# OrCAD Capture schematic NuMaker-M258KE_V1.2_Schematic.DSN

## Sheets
1 Nu-Link2-Me: size A3; title: Nu-Link2-Me; rev: 1.0; company: CMHuang; note: Nu-Link2-Me
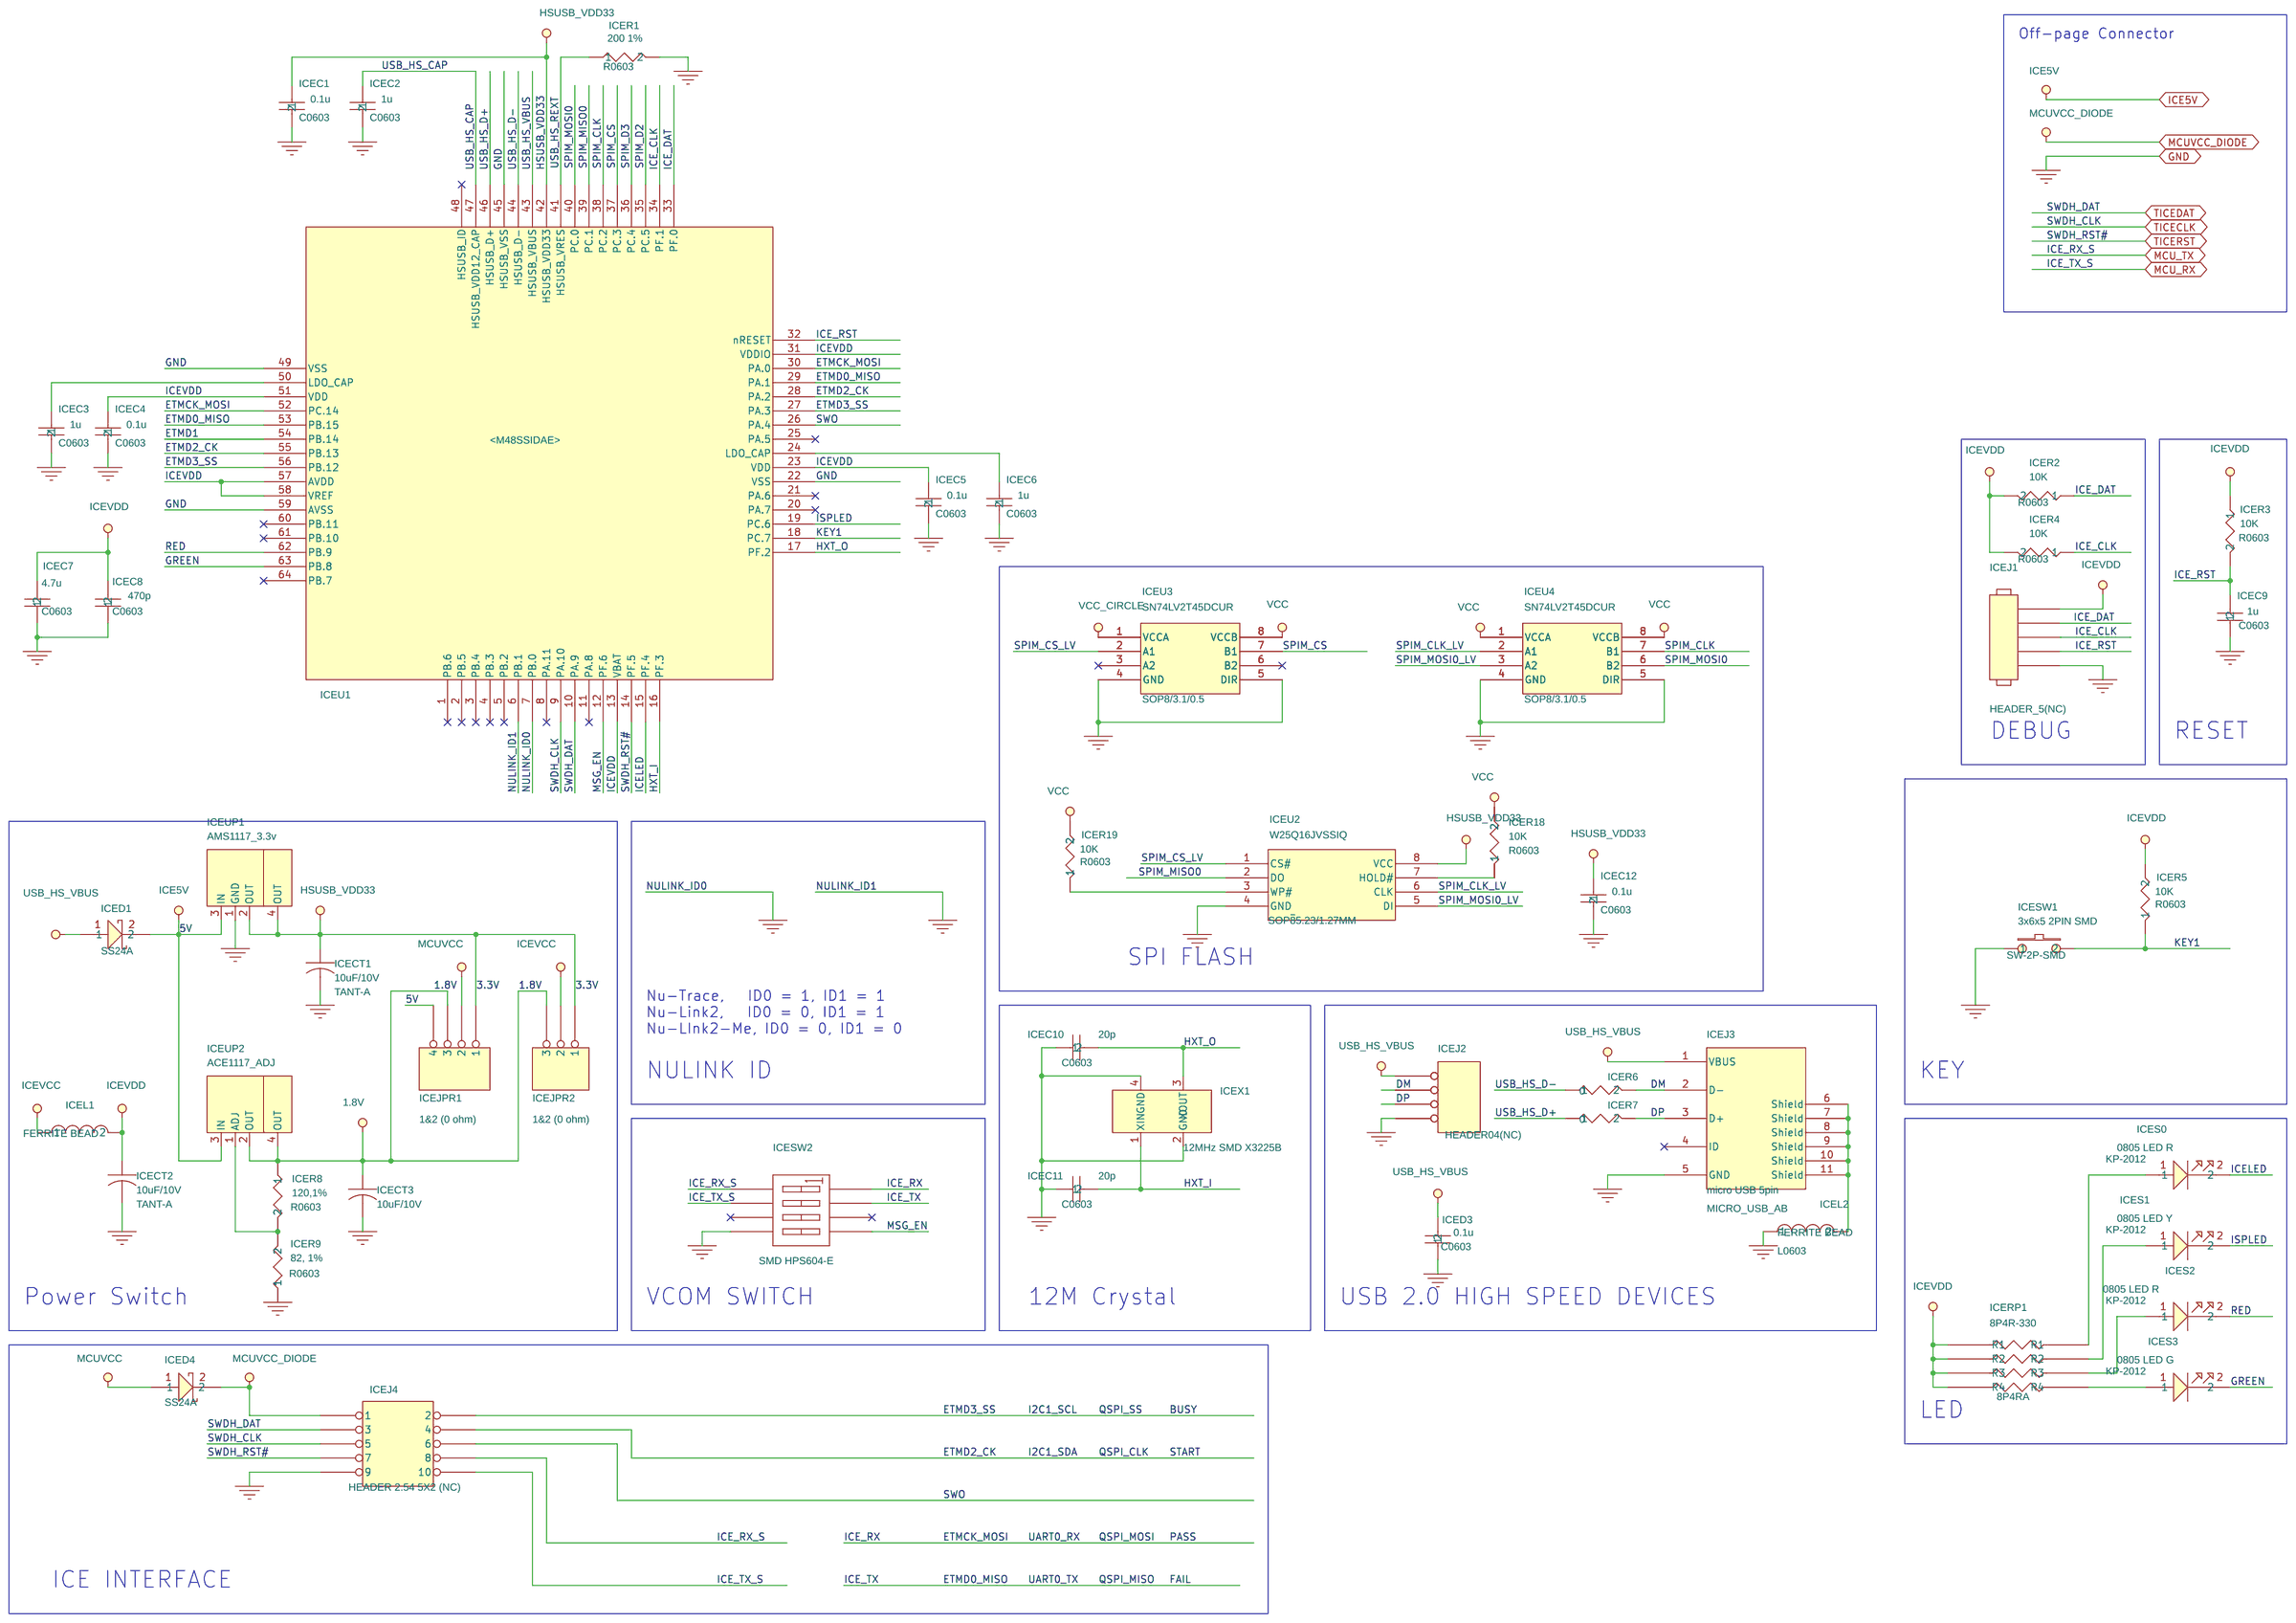
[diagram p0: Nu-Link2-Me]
2 M258KE3AE: size Custom; title: M258KE3AE; rev: v1.2; note: NuMaker-PFM-M258KE
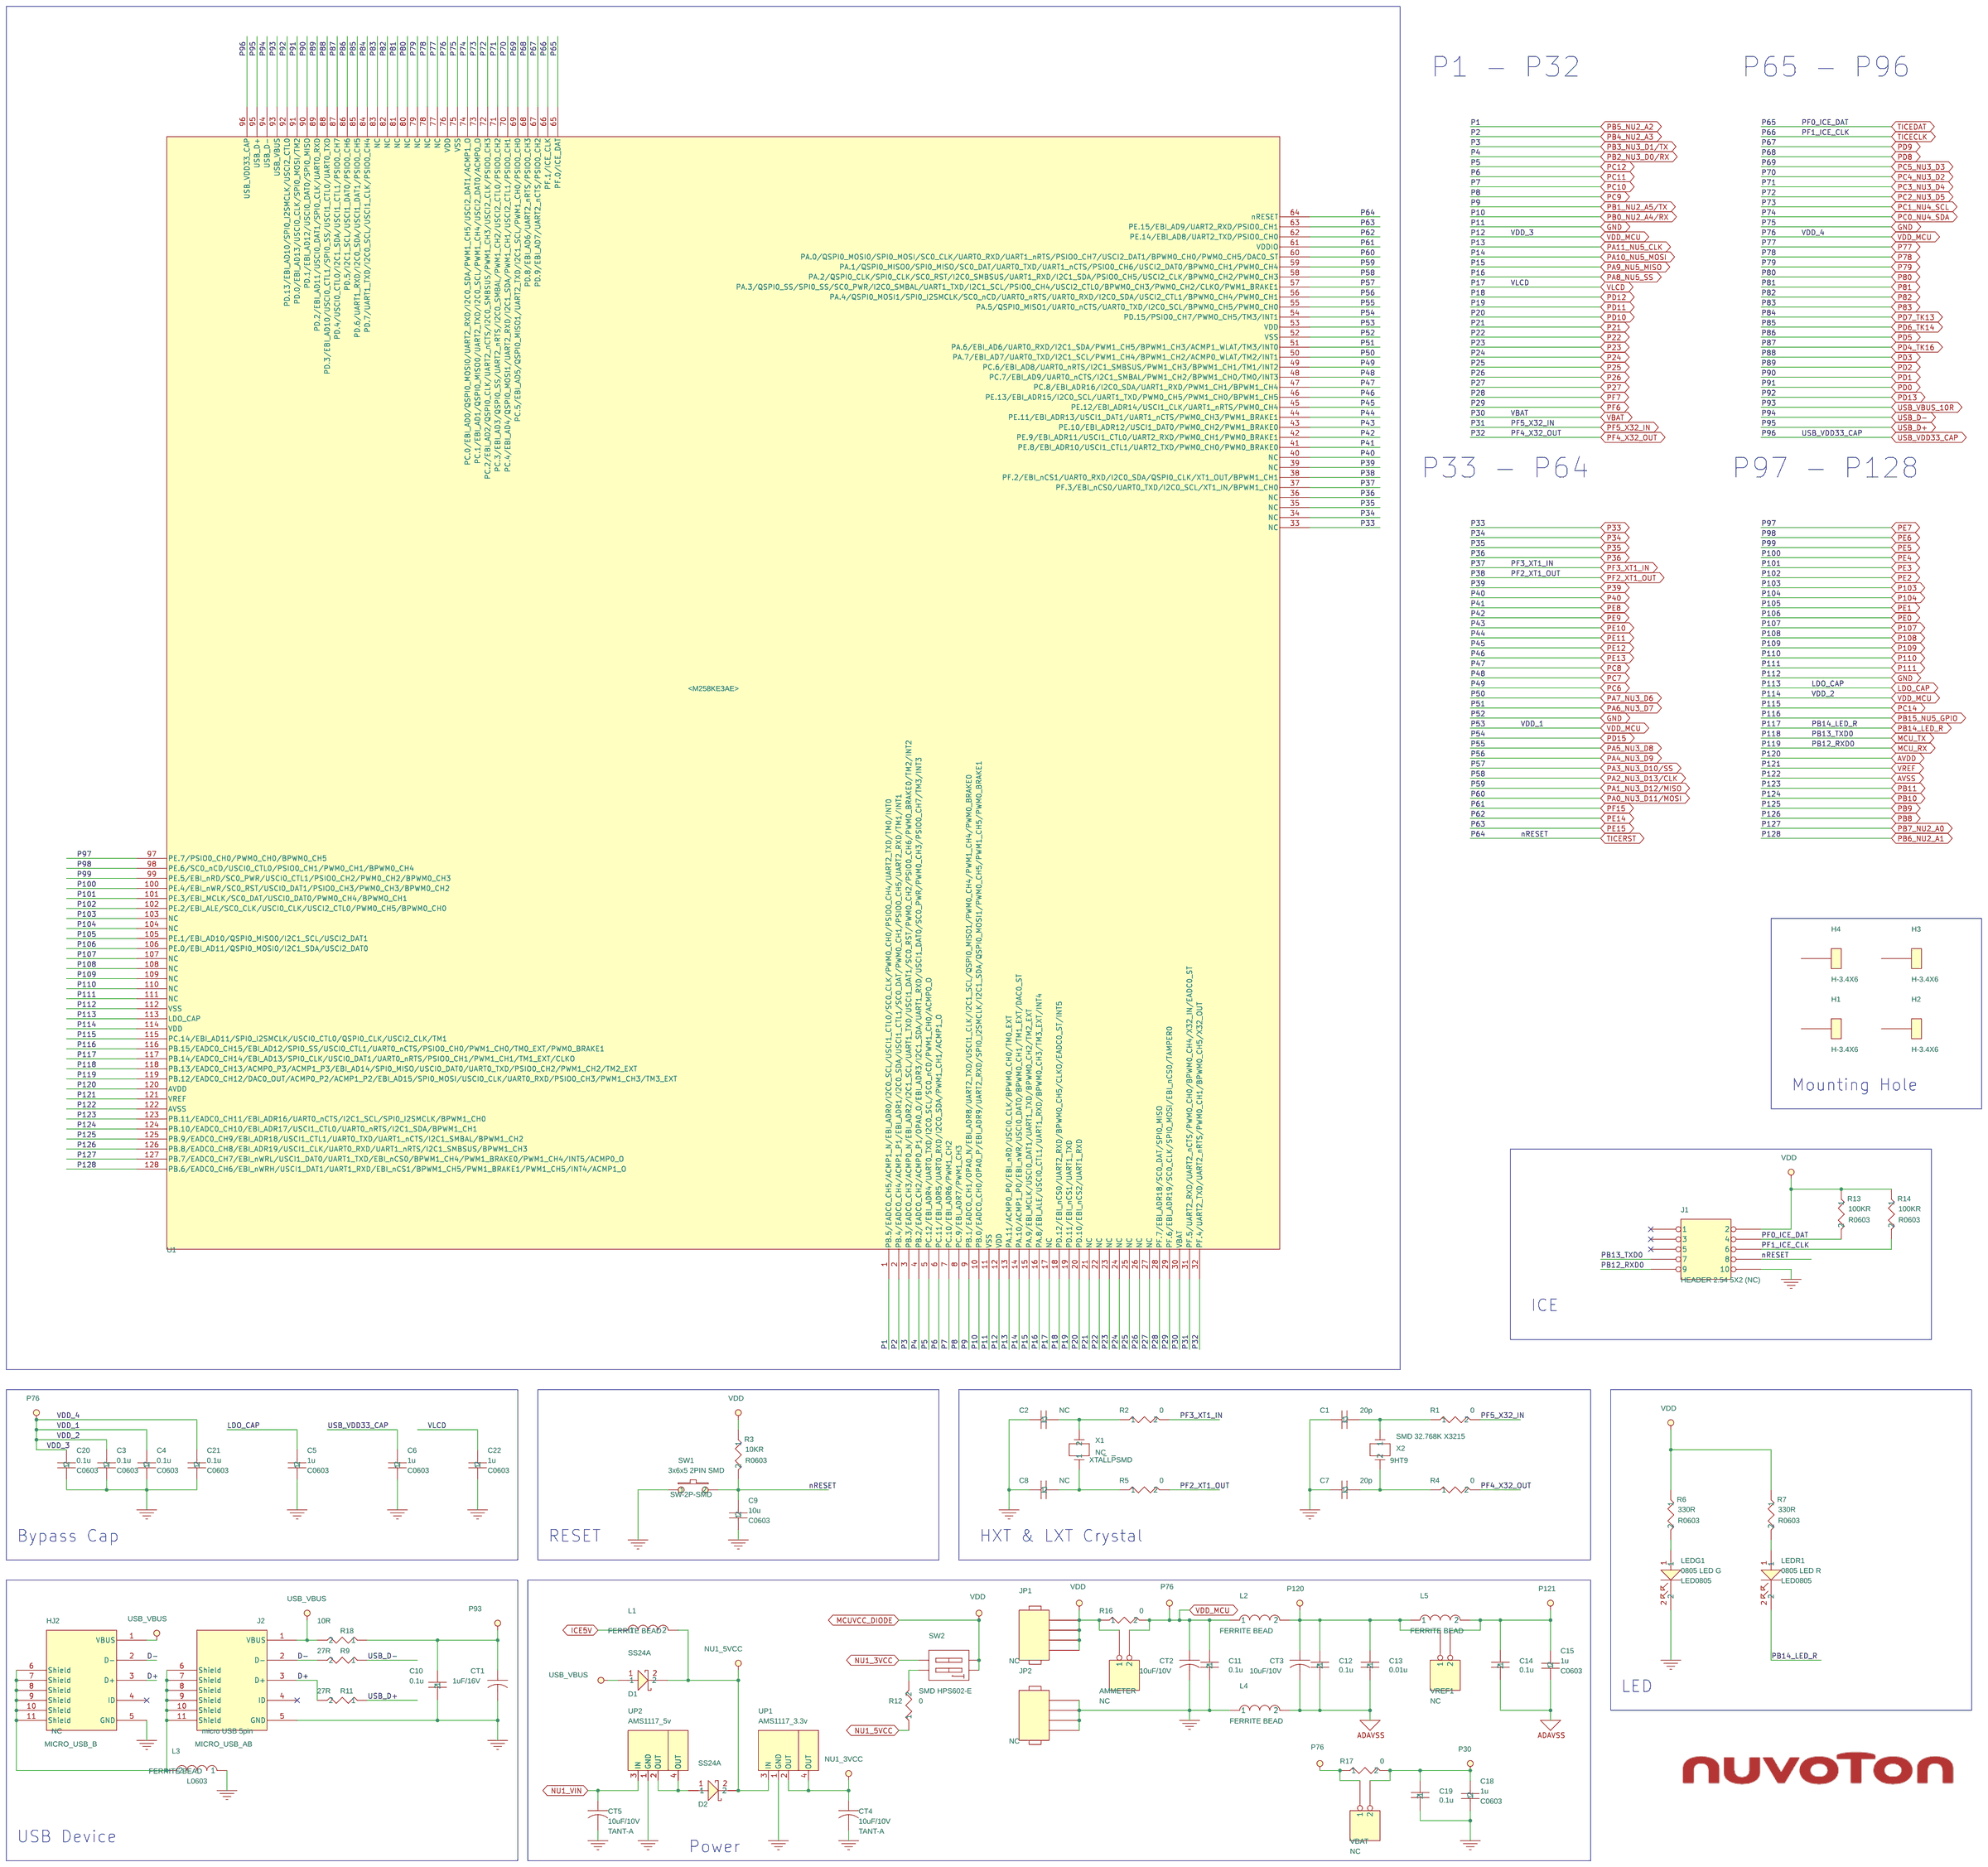
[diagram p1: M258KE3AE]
3 Ext. Connector: size Custom; title: Ext. Connector; rev: v1.2; note: NuMaker-PFM-M258KE
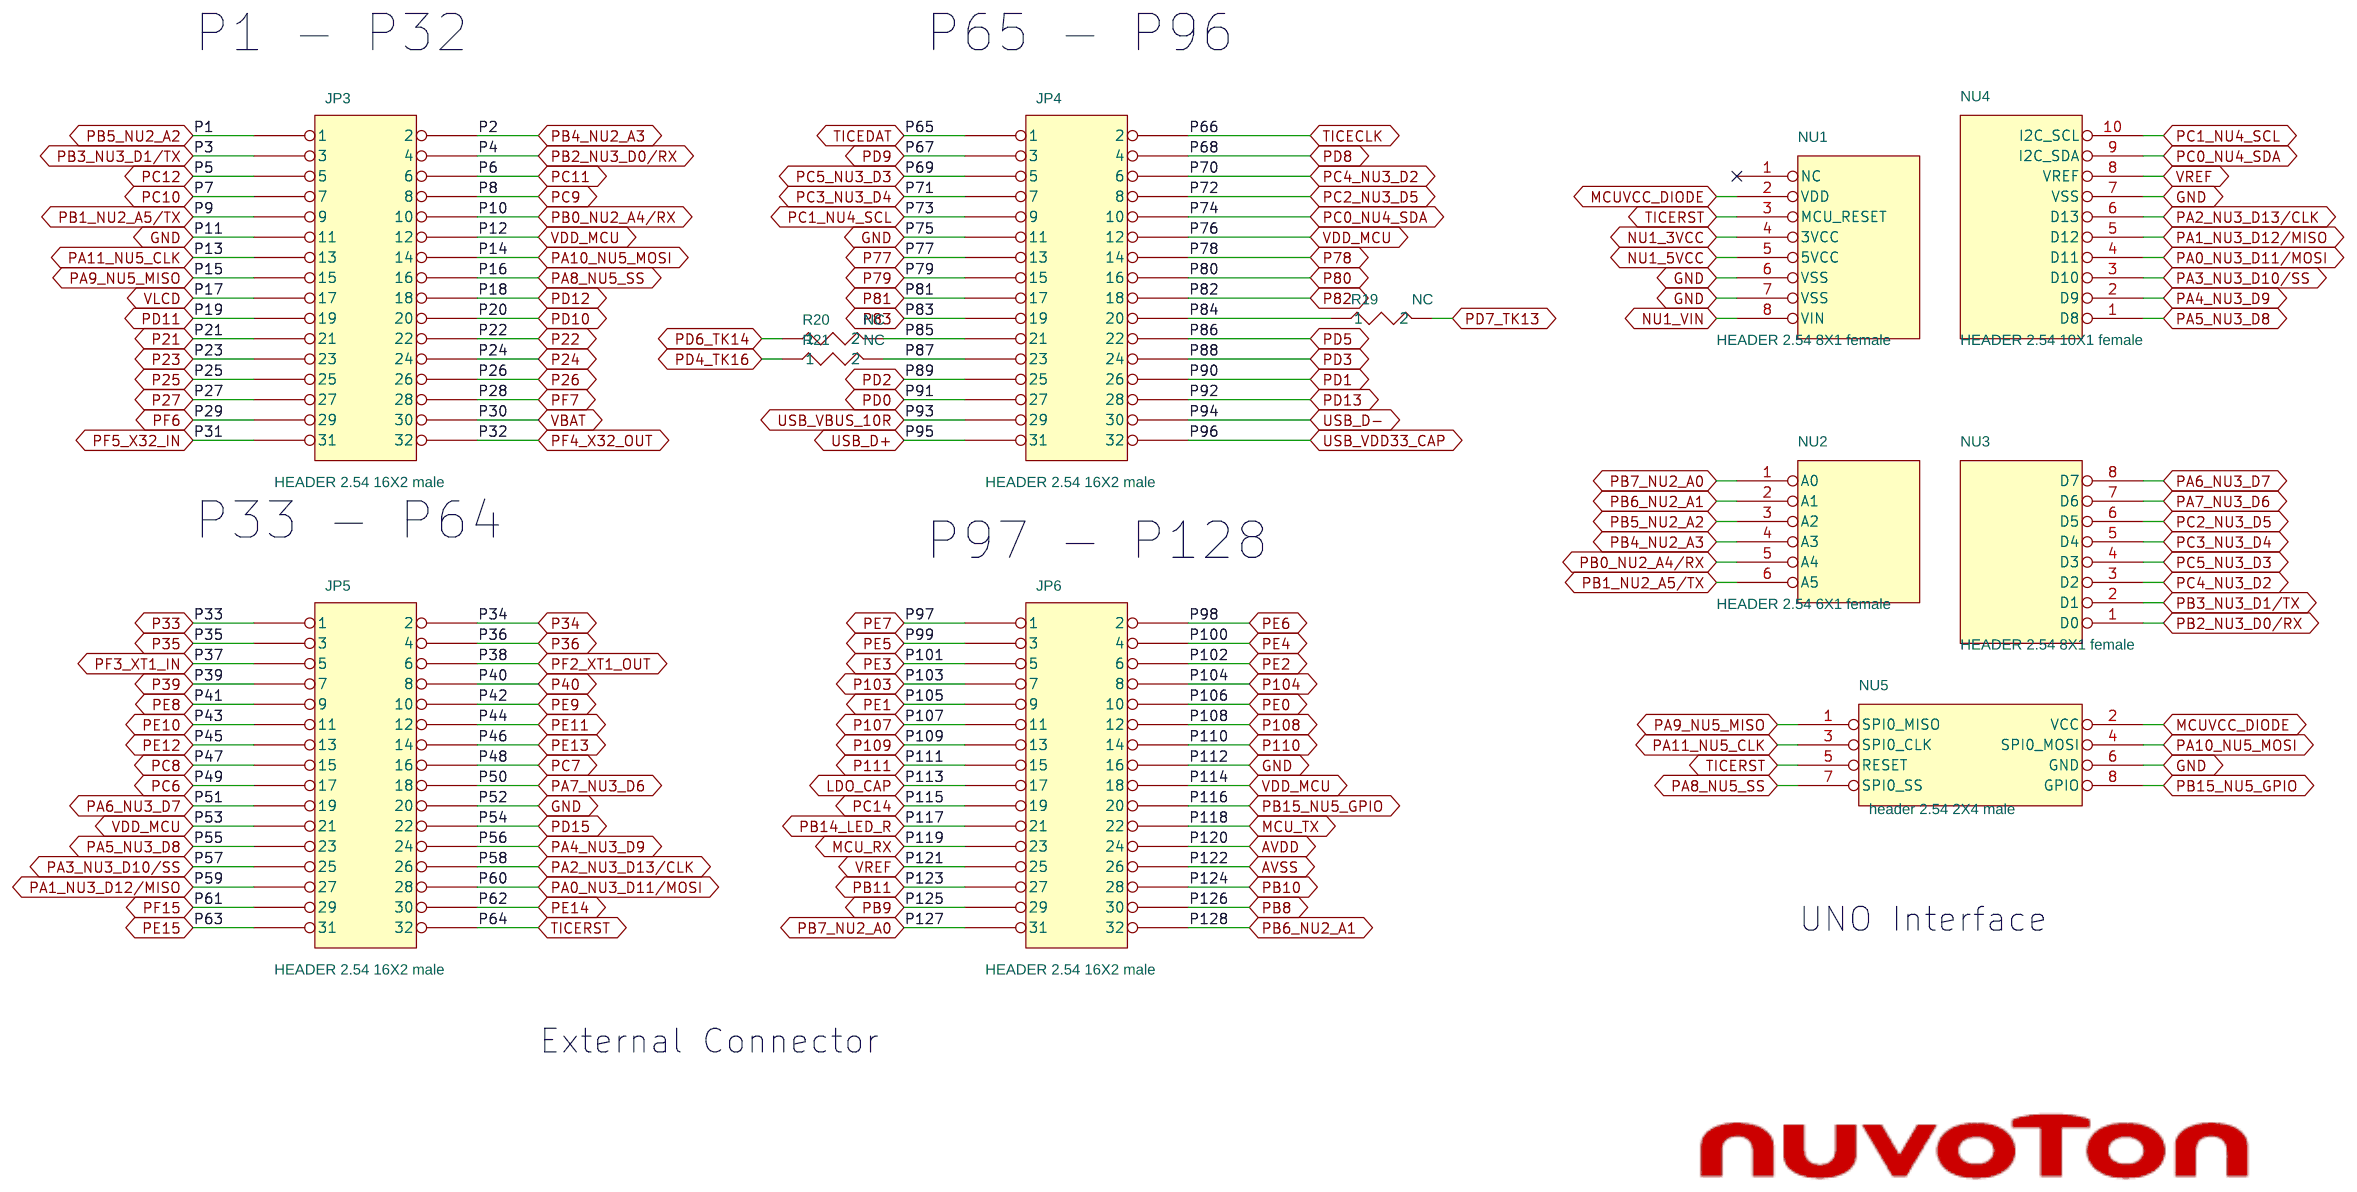
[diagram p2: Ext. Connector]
4 Touch Key: size A; title: Touch Key; rev: v1.2; note: NuMaker-PFM-M258KE
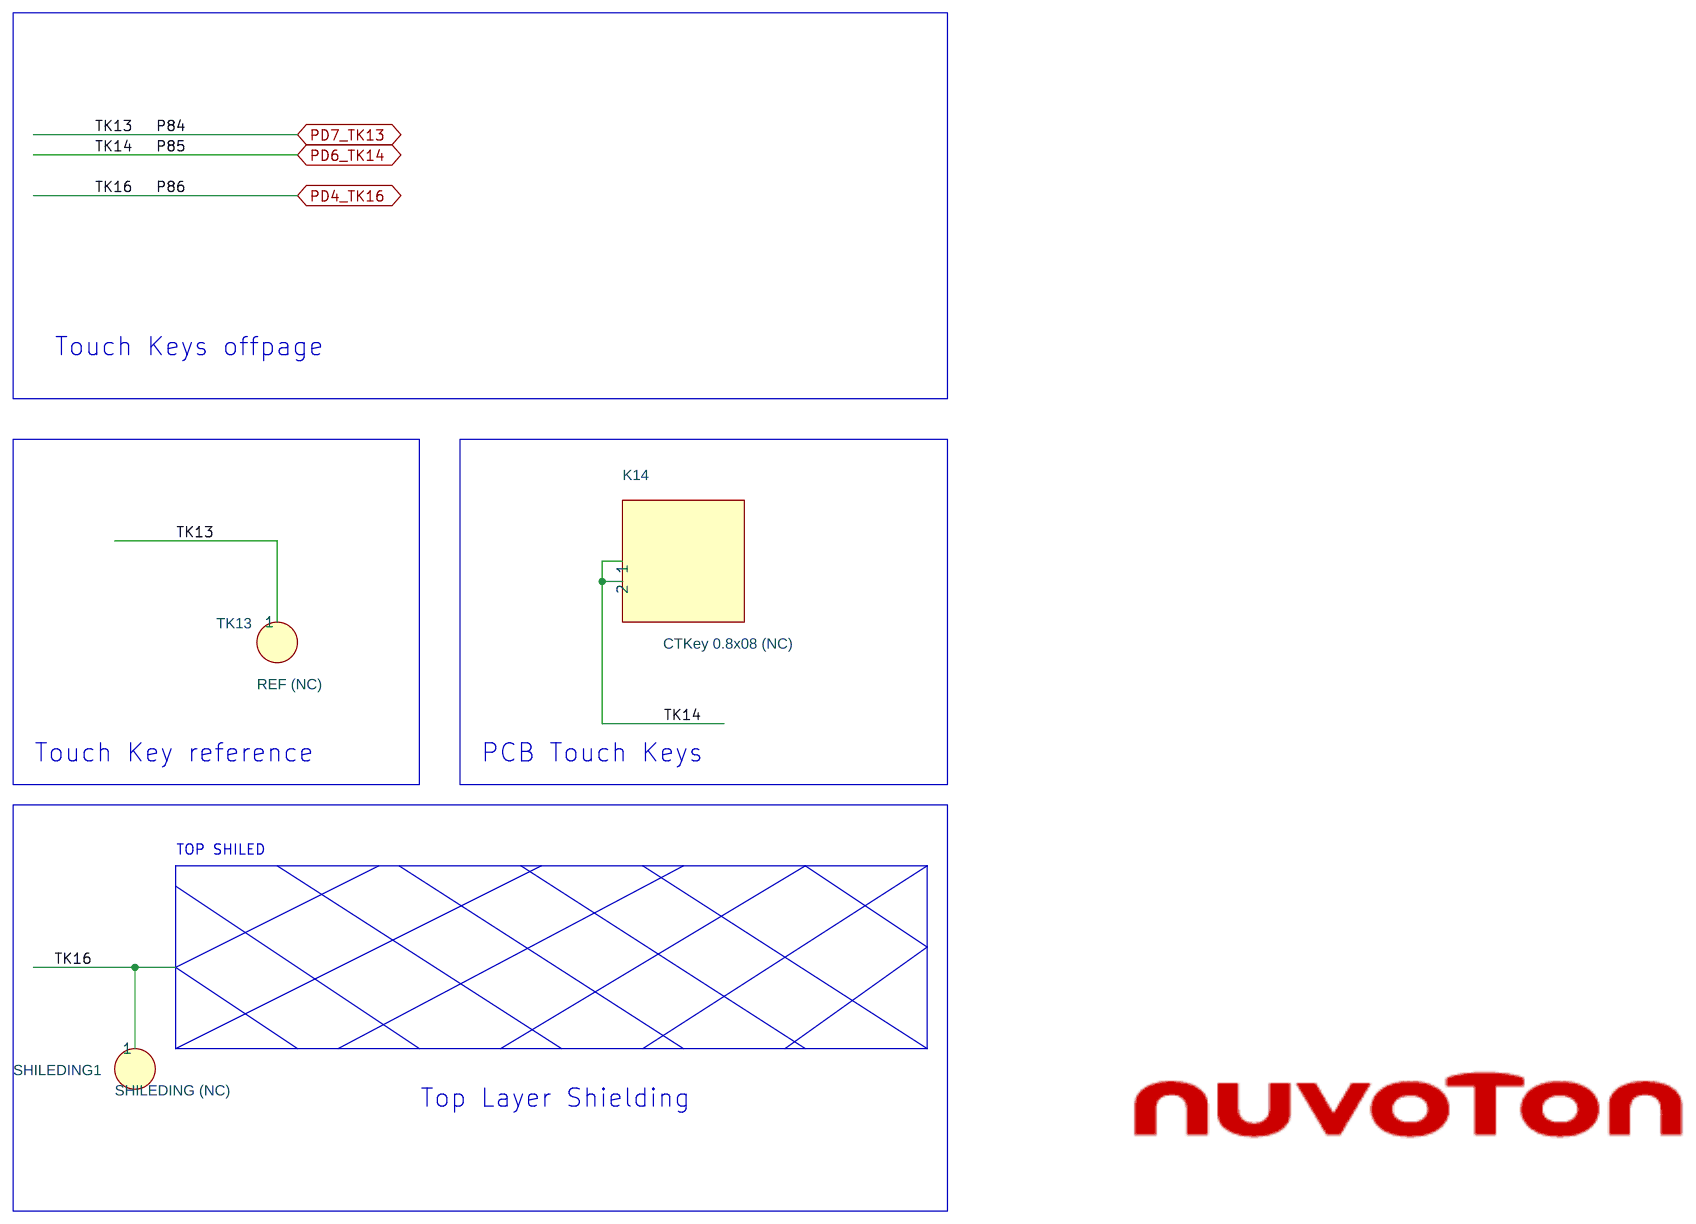
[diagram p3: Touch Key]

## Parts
sheet Ext. Connector
JP3  HEADER 2.54 16X2 male  [HEADER16X2]
JP4  HEADER 2.54 16X2 male  [HEADER16X2]
JP5  HEADER 2.54 16X2 male  [HEADER16X2]
JP6  HEADER 2.54 16X2 male  [HEADER16X2]
NU1  HEADER 2.54 8X1 female  [SIP-8P]
NU2  HEADER 2.54 6X1 female  [SIP-6P]
NU3  HEADER 2.54 8X1 female  [SIP-8P]
NU4  HEADER 2.54 10X1 female  [SIP-10P]
NU5  header 2.54 2X4 male  [HEADER4X2]
R19  NC  [R0603]
R20  NC  [R0603]
R21  NC  [R0603]
sheet M258KE3AE
AMMETER  NC  [HEADER2X1]
C1  20p  [C0603]
C2  NC  [C0603]
C3  0.1u  [C0603]
C4  0.1u  [C0603]
C5  1u  [C0603]
C6  1u  [C0603]
C7  20p  [C0603]
C8  NC  [C0603]
C9  10u  [C0603]
C10  0.1u  [C0603]
C11  0.1u  [C0603]
C12  0.1u  [C0603]
C13  0.01u  [C0603]
C14  0.1u  [C0603]
C15  1u  [C0603]
C18  1u  [C0603]
C19  0.1u  [C0603]
C20  0.1u  [C0603]
C21  0.1u  [C0603]
C22  1u  [C0603]
CT1  1uF/16V  [TANT-A]
CT2  10uF/10V  [TANT-A]
CT3  10uF/10V  [TANT-A]
CT4  10uF/10V  [TANT-A]
CT5  10uF/10V  [TANT-A]
D1  SS24A  [RB060L]
D2  SS24A  [RB060L]
H1  H-3.4X6  [H-3.4X6]
H2  H-3.4X6  [H-3.4X6]
H3  H-3.4X6  [H-3.4X6]
H4  H-3.4X6  [H-3.4X6]
HJ2  NC  [MICRO_USB_B]
J1  HEADER 2.54 5X2 (NC)  [HEADER5X2]
J2  micro USB 5pin  [MICRO_USB_AB]
JP1  NC  [header1x4]
JP2  NC  [header1x4]
L1  FERRITE BEAD  [L0603]
L2  FERRITE BEAD  [L0603]
L3  FERRITE BEAD  [L0603]
L4  FERRITE BEAD  [L0603]
L5  FERRITE BEAD  [L0603]
LEDG1  0805 LED G  [LED0805]
LEDR1  0805 LED R  [LED0805]
R1  0  [R0603]
R2  0  [R0603]
R3  10KR  [R0603]
R4  0  [R0603]
R5  0  [R0603]
R6  330R  [R0603]
R7  330R  [R0603]
R9  27R  [R0603]
R11  27R  [R0603]
R12  0  [R0603]
R13  100KR  [R0603]
R14  100KR  [R0603]
R16  0  [R0603]
R17  0  [R0603]
R18  10R  [R0603]
SW1  3x6x5 2PIN SMD  [SW-2P-SMD]
SW2  SMD HPS602-E  [SW1X2]
U1  M258KE3AE  [MCU_LQFP_128]
UP1  AMS1117_3.3v  [SOT-223-1]
UP2  AMS1117_5v  [SOT-223-1]
VBAT  NC  [HEADER2X1]
VREF1  NC  [HEADER2X1]
X1  NC  [XTAL\LP\SMD]
X2  SMD 32.768K X3215  [9HT9]
sheet Nu-Link2-Me
ICEC1  0.1u  [C0603]
ICEC2  1u  [C0603]
ICEC3  1u  [C0603]
ICEC4  0.1u  [C0603]
ICEC5  0.1u  [C0603]
ICEC6  1u  [C0603]
ICEC7  4.7u  [C0603]
ICEC8  470p  [C0603]
ICEC9  1u  [C0603]
ICEC10  20p  [C0603]
ICEC11  20p  [C0603]
ICEC12  0.1u  [C0603]
ICECT1  10uF/10V  [TANT-A]
ICECT2  10uF/10V  [TANT-A]
ICECT3  10uF/10V  [TANT-A]
ICED1  SS24A  [RB060L]
ICED3  0.1u  [C0603]
ICED4  SS24A  [RB060L]
ICEJ1  HEADER_5(NC)  [HEADER5X1]
ICEJ2  HEADER04(NC)  [HEADER04]
ICEJ3  micro USB 5pin  [MICRO_USB_AB]
ICEJ4  HEADER 2.54 5X2 (NC)  [HEADER5X2]
ICEJPR1  1&2 (0 ohm)  [R0603X3]
ICEJPR2  1&2 (0 ohm)  [R0603X2]
ICEL1  FERRITE BEAD  [L0603]
ICEL2  FERRITE BEAD  [L0603]
ICER1  200 1%  [R0603]
ICER2  10K  [R0603]
ICER3  10K  [R0603]
ICER4  10K  [R0603]
ICER5  10K  [R0603]
ICER6  0  [R0603]
ICER7  0  [R0603]
ICER8  120,1%  [R0603]
ICER9  82, 1%  [R0603]
ICER18  10K  [R0603]
ICER19  10K  [R0603]
ICERP1  8P4R-330  [8P4RA]
ICES0  0805 LED R  [KP-2012]
ICES1  0805 LED Y  [KP-2012]
ICES2  0805 LED R  [KP-2012]
ICES3  0805 LED G  [KP-2012]
ICESW1  3x6x5 2PIN SMD  [SW-2P-SMD]
ICESW2  SMD HPS604-E  [SW1X4]
ICEU1  M48SSIDAE  [LQFP64_7x7_M48SSIDAE]
ICEU2  W25Q16JVSSIQ  [SOP8\5.23/1.27MM]
ICEU3  SN74LV2T45DCUR  [SOP8/3.1/0.5]
ICEU4  SN74LV2T45DCUR  [SOP8/3.1/0.5]
ICEUP1  AMS1117_3.3v  [SOT-223-1]
ICEUP2  ACE1117_ADJ  [SOT-223-1]
ICEX1  12MHz SMD X3225B  [CRYSTAL_SMD]
sheet Touch Key
K14  CTKey 0.8x08 (NC)  [PAD_8mm]
SHILEDING1  SHILEDING (NC)  [PAD1mm]
TK13  REF (NC)  [PAD1mm]

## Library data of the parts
JP3 = HEADER_16X2_2
JP4 = HEADER_16X2
JP5 = HEADER_16X2_3
JP6 = HEADER_16X2_1
NU1 = POWER_CONNECT_0
NU2 = ADC_CONNECT_1
NU3 = PWM0_CONNECT_0
NU4 = PWM1_CONNECT_1
NU5 = NuEdu_NU7
R16 R19 = R_0
R1 R20 = R_0_1
R21 = R_0_2
AMMETER = HEADER_2_2
C1 = C_20p_3
C2 = C_20p
C3 ICEC12 = CAP-C_8: Package: 0603; element_no: C0004
C4 ICED3 = CAP-C_1: Package: 0603; element_no: C0004
C5 = CAP-C_6: Package: 0603; element_no: C0006
C6 = CAP-C_5: Package: 0603; element_no: C0006
C7 = C_20p_1
C8 = C_20p_2
C9 ICEC2 = CAP-C_9: Package: 0603; element_no: C0006
C10 = C_0.1u_4: element_no: C0004
C11 = C_0.1u_1: element_no: C0004
C12 = C_0.1u_3: element_no: C0004
C13 = C_0.1u_5: element_no: C0003
C14 = C_0.1u_2: element_no: C0004
C15 ICEC9 = CAP-C_7: Package: 0603; element_no: C0006
C18 = CAP-C_4: Package: 0603; element_no: C0006
C19 = C_0.1u: element_no: C0004
C20 = CAP-C_2: Package: 0603; element_no: C0004
C21 ICEC5 = CAP-C: Package: 0603; element_no: C0004
C22 = CAP-C_3: Package: 0603; element_no: C0006
CT1 = C_1uF_16V
CT2-CT5 ICECT1-ICECT3 = C_10uF_10V
D1 ICED1 = D_SS24A_1
D2 ICED4 = D_SS24A
H1-H4 = TEST_POINT
HJ2 ICEJ3 J2 = micro_USB_5pin_0
ICEJ4 J1 = HEADER_5X2
JP1 JP2 = HEADER_4
L1 = FERRITE_BEAD_3
L2 = FERRITE_BEAD_2
L3 = FERRITE_BEAD_4
ICEL2 L4 = FERRITE_BEAD_1
ICEL1 L5 = FERRITE_BEAD
LEDG1 = LED_0_1: Package: KP-2012; Vendor: Kingbright
LEDR1 = LED_0: Package: KP-2012; Vendor: Kingbright
R2 = R_0_4
ICER1 R3 = R_0_5: Package: 0603
R4 = R_0_11
R5 = R_0_3
ICER19 R6 = R_0_7: Package: 0603
ICER9 R7 = R_0_2: Package: 0603
ICER7 R9 = R_33_1
ICER6 R11 = R_33
R12 = R_0_8
ICER18 R13 = R_0_6: Package: 0603
R14 = R_0_9: Package: 0603
R17 = R_0_10
R18 = R_33_2
ICESW1 SW1 = SW_PUSHBUTTON_0
SW2 = SW_DIP-4_2
U1 = M252KG6AE: M252KG6AE: <M258KE3AE>
ICEUP1 UP1 UP2 = TO-247_Regulator_10
VBAT = HEADER_2
VREF1 = HEADER_2_1
X1 = Xtal_12MHz
X2 = Xtal_32.768K
ICEC1 = CAP-C_11: Package: 0603; element_no: C0004
ICEC3 = CAP-C_2: Package: 0603; element_no: C0006
ICEC4 = CAP-C_10: Package: 0603; element_no: C0004
ICEC6 = CAP-C_12: Package: 0603; element_no: C0006
ICEC7 = CAP-C_5: Package: 0603
ICEC8 = CAP-C_6: Package: 0603
ICEC10 = CAP-C_3: Package: 0603
ICEC11 = CAP-C_4: Package: 0603
ICEJ1 = HEADER_5_v2
ICEJ2 = HEADER_4_v2
ICEJPR1 = HEADER_3_0
ICEJPR2 = HEADER_3
ICER2 = R_0_1: Package: 0603
ICER3 = R_0_4: Package: 0603
ICER4 = R_0_3: Package: 0603
ICER5 = R_0_8: Package: 0603
ICER8 = R_0: Package: 0603
ICERP1 = R-PACK8_0
ICES0 = LED_0_3: Vendor: Kingbright
ICES1 = LED_0_2: Vendor: Kingbright
ICES2 = LED_0_1: Vendor: Kingbright
ICES3 = LED_0: Vendor: Kingbright
ICESW2 = SW_DIP-4_SM
ICEU1 = M487SIDAE_0: M487SIDAE: <M48SSIDAE>
ICEU2 = W25P10_20_40_SOIC_0: Package: SOP8; Vendor: WINBOND
ICEU3 ICEU4 = SN74LV2T45
ICEUP2 = TO-247_Regulator_0
ICEX1 = Crystal_SMD_1
K14 = CTKey_0
SHILEDING1 TK13 = CTKey_7

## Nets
1.8V: ICECT3.1 ICEJPR1.3 ICEJPR2.3 ICER8.1 ICEUP2.2(OUT) ICEUP2.4(OUT)
3.3V: ICEC1.1 ICEC12.1 ICECT1.1 ICEJPR1.1 ICEJPR2.1 ICER18.2 ICER19.2 ICEU1.42(HSUSB_VDD33) ICEU2.8(VCC) ICEU3.1(VCCA) ICEU4.1(VCCA) ICEUP1.2(OUT) ICEUP1.4(OUT)
AVDD: C12.1 C13.1 CT3.1 JP6.24 L2.2 L5.1 U1.120(AVDD) VREF1.1
AVSS: C12.2 C13.2 C14.2 C15.1 CT3.2 JP6.26 L4.2 U1.122(AVSS)
GND: C1.1 C2.1 C3.1 C4.1 C5.1 C6.1 C7.1 C8.1 C9.1 C10.2 C11.2 C18.1 C19.2 C20.1 C21.1 C22.1 CT1.2 CT2.2 CT4.2 CT5.2 HJ2.5(GND) ICEC1.2 ICEC2.2 ICEC3.2 ICEC4.2 ICEC5.2 ICEC6.2 ICEC7.1 ICEC8.1 ICEC9.1 ICEC10.1 ICEC11.1 ICEC12.2 ICECT1.2 ICECT2.2 ICECT3.2 ICED3.1 ICEJ1.5 ICEJ2.4 ICEJ3.5(GND) ICEJ4.9 ICEL2.1 ICER1.2 ICER9.1 ICESW1.1 ICESW2.4(A4) ICEU1.6(PB.1) ICEU1.7(PB.0) ICEU1.22(VSS) ICEU1.45(HSUSB_VSS) ICEU1.49(VSS) ICEU1.59(AVSS) ICEU2.4(GND) ICEU3.4(GND) ICEU3.5(DIR) ICEU4.4(GND) ICEU4.5(DIR) ICEUP1.1(GND) ICEX1.2(GND) ICEX1.4(GND) J1.10 J2.5(GND) JP2.1 JP2.2 JP2.3 JP2.4 JP3.11 JP4.11 JP5.20 JP6.16 L3.1 L4.1 LEDG1.2 NU1.6(VSS) NU1.7(VSS) NU4.7(VSS) NU5.6(GND) SW1.1 U1.11(VSS) U1.52(VSS) U1.75(VSS) U1.112(VSS) UP1.1(GND) UP2.1(GND)
VBAT: C18.2 C19.1 JP3.30 R17.2 U1.30(VBAT) VBAT.2
VDD: AMMETER.1 ICED4.2 ICEJ4.1 J1.2 JP1.1 JP1.2 JP1.3 JP1.4 NU1.2(VDD) NU5.2(VCC) R3.1 R6.1 R7.1 R13.1 R14.1 R16.1 SW2.3(B1) SW2.4(B2)
VDD_MCU: AMMETER.2 C3.2 C4.2 C11.1 C20.2 C21.2 CT2.1 JP3.12 JP4.12 JP5.21 JP6.18 L2.1 R16.2 R17.1 U1.12(VDD) U1.53(VDD) U1.76(VDD) U1.114(VDD) VBAT.1
BUSY: ICEJ4.2 ICEU1.27(PA.3) ICEU1.56(PB.12)
D+: HJ2.3(D+) J2.3(D+) R11.2
D-: HJ2.2(D-) J2.2(D-) R9.2
DM: ICEJ2.2 ICEJ3.2(D-) ICER6.2
DP: ICEJ2.3 ICEJ3.3(D+) ICER7.2
ETMD1: ICEU1.54(PB.14)
ETMD2_CK: ICEJ4.4 ICEU1.28(PA.2) ICEU1.55(PB.13)
GREEN: ICES3.2 ICEU1.63(PB.8)
HXT_I: ICEC11.2 ICEU1.16(PF.3) ICEX1.1(XIN)
HXT_O: ICEC10.2 ICEU1.17(PF.2) ICEX1.3(XOUT)
ICE5V: ICED1.2 ICEJPR1.4 ICEUP1.3(IN) ICEUP2.3(IN) L1.1
ICE_CLK: ICEJ1.3 ICER4.1 ICEU1.34(PF.1)
ICE_DAT: ICEJ1.2 ICER2.1 ICEU1.33(PF.0)
ICE_RST: ICEC9.2 ICEJ1.4 ICER3.2 ICEU1.32(nRESET)
ICE_RX: ICESW2.8(B1) ICEU1.30(PA.0) ICEU1.52(PC.14)
ICE_TX: ICESW2.7(B2) ICEU1.29(PA.1) ICEU1.53(PB.15)
ICELED: ICES0.2 ICEU1.15(PF.4)
ICEVCC: ICEJPR2.2 ICEL1.1
ICEVDD: ICEC4.1 ICEC5.1 ICEC7.2 ICEC8.2 ICECT2.1 ICEJ1.1 ICEL1.2 ICER2.2 ICER3.1 ICER4.2 ICER5.2 ICERP1.1(R1) ICERP1.3(R2) ICERP1.5(R3) ICERP1.7(R4) ICEU1.13(VBAT) ICEU1.23(VDD) ICEU1.31(VDDIO) ICEU1.51(VDD) ICEU1.57(AVDD) ICEU1.58(VREF) ICEU3.8(VCCB) ICEU4.8(VCCB)
ISPLED: ICES1.2 ICEU1.19(PC.6)
KEY1: ICER5.1 ICESW1.2 ICEU1.18(PC.7)
LDO_CAP: C5.2 JP6.17 U1.113(LDO_CAP)
MCU_RX: ICEJ4.10 ICESW2.2(A2) J1.9 JP6.23 U1.119(PB.12/EADC0_CH12/DAC0_OUT/ACMP0_P2/ACMP1_P2/EBI_AD15/SPI0_MOSI/USCI0_CLK/UART0_RXD/PSIO0_CH3/PWM1_CH3/TM3_EXT)
MCU_TX: ICEJ4.8 ICESW2.1(A1) J1.7 JP6.22 U1.118(PB.13/EADC0_CH13/ACMP0_P3/ACMP1_P3/EBI_AD14/SPI0_MISO/USCI0_DAT0/UART0_TXD/PSIO0_CH2/PWM1_CH2/TM2_EXT)
MCUVCC: ICED4.1 ICEJPR1.2
MSG_EN: ICESW2.5(B4) ICEU1.12(PF.6)
NU1_3VCC: CT4.1 NU1.4(3VCC) SW2.2(A2) UP1.2(OUT) UP1.4(OUT)
NU1_5VCC: D1.2 D2.2 L1.2 NU1.5(5VCC) R12.1 UP1.3(IN)
NU1_VIN: CT5.1 NU1.8(VIN) UP2.3(IN)
P21: JP3.21 U1.21(NC)
P22: JP3.22 U1.22(NC)
P23: JP3.23 U1.23(NC)
P24: JP3.24 U1.24(NC)
P25: JP3.25 U1.25(NC)
P26: JP3.26 U1.26(NC)
P27: JP3.27 U1.27(NC)
P33: JP5.1 U1.33(NC)
P34: JP5.2 U1.34(NC)
P35: JP5.3 U1.35(NC)
P36: JP5.4 U1.36(NC)
P39: JP5.7 U1.39(NC)
P40: JP5.8 U1.40(NC)
P77: JP4.13 U1.77(NC)
P78: JP4.14 U1.78(NC)
P79: JP4.15 U1.79(NC)
P80: JP4.16 U1.80(NC)
P81: JP4.17 U1.81(NC)
P82: JP4.18 U1.82(NC)
P83: JP4.19 U1.83(NC)
P84: JP4.20 R19.1
P85: JP4.21 R20.2
P87: JP4.23 R21.2
P103: JP6.7 U1.103(NC)
P104: JP6.8 U1.104(NC)
P107: JP6.11 U1.107(NC)
P108: JP6.12 U1.108(NC)
P109: JP6.13 U1.109(NC)
P110: JP6.14 U1.110(NC)
P111: JP6.15 U1.111(NC)
PA0_NU3_D11/MOSI: JP5.28 NU4.4(D11) U1.60(PA.0/QSPI0_MOSI0/SPI0_MOSI/SC0_CLK/UART0_RXD/UART1_nRTS/PSIO0_CH7/USCI2_DAT1/BPWM0_CH0/PWM0_CH5/DAC0_ST)
PA1_NU3_D12/MISO: JP5.27 NU4.5(D12) U1.59(PA.1/QSPI0_MISO0/SPI0_MISO/SC0_DAT/UART0_TXD/UART1_nCTS/PSIO0_CH6/USCI2_DAT0/BPWM0_CH1/PWM0_CH4)
PA2_NU3_D13/CLK: JP5.26 NU4.6(D13) U1.58(PA.2/QSPI0_CLK/SPI0_CLK/SC0_RST/I2C0_SMBSUS/UART1_RXD/I2C1_SDA/PSIO0_CH5/USCI2_CLK/BPWM0_CH2/PWM0_CH3)
PA3_NU3_D10/SS: JP5.25 NU4.3(D10) U1.57(PA.3/QSPI0_SS/SPI0_SS/SC0_PWR/I2C0_SMBAL/UART1_TXD/I2C1_SCL/PSIO0_CH4/USCI2_CTL0/BPWM0_CH3/PWM0_CH2/CLKO/PWM1_BRAKE1)
PA4_NU3_D9: JP5.24 NU4.2(D9) U1.56(PA.4/QSPI0_MOSI1/SPI0_I2SMCLK/SC0_nCD/UART0_nRTS/UART0_RXD/I2C0_SDA/USCI2_CTL1/BPWM0_CH4/PWM0_CH1)
PA5_NU3_D8: JP5.23 NU4.1(D8) U1.55(PA.5/QSPI0_MISO1/UART0_nCTS/UART0_TXD/I2C0_SCL/BPWM0_CH5/PWM0_CH0)
PA6_NU3_D7: JP5.19 NU3.8(D7) U1.51(PA.6/EBI_AD6/UART0_RXD/I2C1_SDA/PWM1_CH5/BPWM1_CH3/ACMP1_WLAT/TM3/INT0)
PA7_NU3_D6: JP5.18 NU3.7(D6) U1.50(PA.7/EBI_AD7/UART0_TXD/I2C1_SCL/PWM1_CH4/BPWM1_CH2/ACMP0_WLAT/TM2/INT1)
PA8_NU5_SS: JP3.16 NU5.7(SPI0_SS) U1.16(PA.8/EBI_ALE/USCI0_CTL1/UART1_RXD/BPWM0_CH3/TM3_EXT/INT4)
PA9_NU5_MISO: JP3.15 NU5.1(SPI0_MISO) U1.15(PA.9/EBI_MCLK/USCI0_DAT1/UART1_TXD/BPWM0_CH2/TM2_EXT)
PA10_NU5_MOSI: JP3.14 NU5.4(SPI0_MOSI) U1.14(PA.10/ACMP1_P0/EBI_nWR/USCI0_DAT0/BPWM0_CH1/TM1_EXT/DAC0_ST)
PA11_NU5_CLK: JP3.13 NU5.3(SPI0_CLK) U1.13(PA.11/ACMP0_P0/EBI_nRD/USCI0_CLK/BPWM0_CH0/TM0_EXT)
PB0_NU2_A4/RX: JP3.10 NU2.5(A4) U1.10(PB.0/EADC0_CH0/OPA0_P/EBI_ADR9/UART2_RXD/SPI0_I2SMCLK/I2C1_SDA/QSPI0_MOSI1/PWM0_CH5/PWM1_CH5/PWM0_BRAKE1)
PB1_NU2_A5/TX: JP3.9 NU2.6(A5) U1.9(PB.1/EADC0_CH1/OPA0_N/EBI_ADR8/UART2_TXD/USCI1_CLK/I2C1_SCL/QSPI0_MISO1/PWM0_CH4/PWM1_CH4/PWM0_BRAKE0)
PB2_NU3_D0/RX: JP3.4 NU3.1(D0) U1.4(PB.2/EADC0_CH2/ACMP0_P1/OPA0_O/EBI_ADR3/I2C1_SDA/UART1_RXD/USCI1_DAT0/SC0_PWR/PWM0_CH3/PSIO0_CH7/TM3/INT3)
PB3_NU3_D1/TX: JP3.3 NU3.2(D1) U1.3(PB.3/EADC0_CH3/ACMP0_N/EBI_ADR2/I2C1_SCL/UART1_TXD/USCI1_DAT1/SC0_RST/PWM0_CH2/PSIO0_CH6/PWM0_BRAKE0/TM2/INT2)
PB4_NU2_A3: JP3.2 NU2.4(A3) U1.2(PB.4/EADC0_CH4/ACMP1_P1/EBI_ADR1/I2C0_SDA/USCI1_CTL1/SC0_DAT/PWM0_CH1/PSIO0_CH5/UART2_RXD/TM1/INT1)
PB5_NU2_A2: JP3.1 NU2.3(A2) U1.1(PB.5/EADC0_CH5/ACMP1_N/EBI_ADR0/I2C0_SCL/USCI1_CTL0/SC0_CLK/PWM0_CH0/PSIO0_CH4/UART2_TXD/TM0/INT0)
PB6_NU2_A1: JP6.32 NU2.2(A1) U1.128(PB.6/EADC0_CH6/EBI_nWRH/USCI1_DAT1/UART1_RXD/EBI_nCS1/BPWM1_CH5/PWM1_BRAKE1/PWM1_CH5/INT4/ACMP1_O)
PB7_NU2_A0: JP6.31 NU2.1(A0) U1.127(PB.7/EADC0_CH7/EBI_nWRL/USCI1_DAT0/UART1_TXD/EBI_nCS0/BPWM1_CH4/PWM1_BRAKE0/PWM1_CH4/INT5/ACMP0_O)
PB8: JP6.30 U1.126(PB.8/EADC0_CH8/EBI_ADR19/USCI1_CLK/UART0_RXD/UART1_nRTS/I2C1_SMBSUS/BPWM1_CH3)
PB9: JP6.29 U1.125(PB.9/EADC0_CH9/EBI_ADR18/USCI1_CTL1/UART0_TXD/UART1_nCTS/I2C1_SMBAL/BPWM1_CH2)
PB10: JP6.28 U1.124(PB.10/EADC0_CH10/EBI_ADR17/USCI1_CTL0/UART0_nRTS/I2C1_SDA/BPWM1_CH1)
PB11: JP6.27 U1.123(PB.11/EADC0_CH11/EBI_ADR16/UART0_nCTS/I2C1_SCL/SPI0_I2SMCLK/BPWM1_CH0)
PB14_LED_R: JP6.21 LEDR1.2 U1.117(PB.14/EADC0_CH14/EBI_AD13/SPI0_CLK/USCI0_DAT1/UART0_nRTS/PSIO0_CH1/PWM1_CH1/TM1_EXT/CLKO)
PB15_NU5_GPIO: JP6.20 NU5.8(GPIO) U1.116(PB.15/EADC0_CH15/EBI_AD12/SPI0_SS/USCI0_CTL1/UART0_nCTS/PSIO0_CH0/PWM1_CH0/TM0_EXT/PWM0_BRAKE1)
PC0_NU4_SDA: JP4.10 NU4.9(I2C_SDA) U1.74(PC.0/EBI_AD0/QSPI0_MOSI0/UART2_RXD/I2C0_SDA/PWM1_CH5/USCI2_DAT1/ACMP1_O)
PC1_NU4_SCL: JP4.9 NU4.10(I2C_SCL) U1.73(PC.1/EBI_AD1/QSPI0_MISO0/UART2_TXD/I2C0_SCL/PWM1_CH4/USCI2_DAT0/ACMP0_O)
PC2_NU3_D5: JP4.8 NU3.6(D5) U1.72(PC.2/EBI_AD2/QSPI0_CLK/UART2_nCTS/I2C0_SMBSUS/PWM1_CH3/USCI2_CLK/PSIO0_CH3)
PC3_NU3_D4: JP4.7 NU3.5(D4) U1.71(PC.3/EBI_AD3/QSPI0_SS/UART2_nRTS/I2C0_SMBAL/PWM1_CH2/USCI2_CTL0/PSIO0_CH2)
PC4_NU3_D2: JP4.6 NU3.3(D2) U1.70(PC.4/EBI_AD4/QSPI0_MOSI1/UART2_RXD/I2C1_SDA/PWM1_CH1/USCI2_CTL1/PSIO0_CH1)
PC5_NU3_D3: JP4.5 NU3.4(D3) U1.69(PC.5/EBI_AD5/QSPI0_MISO1/UART2_TXD/I2C1_SCL/PWM1_CH0/PSIO0_CH0)
PC6: JP5.17 U1.49(PC.6/EBI_AD8/UART0_nRTS/I2C1_SMBSUS/PWM1_CH3/BPWM1_CH1/TM1/INT2)
PC7: JP5.16 U1.48(PC.7/EBI_AD9/UART0_nCTS/I2C1_SMBAL/PWM1_CH2/BPWM1_CH0/TM0/INT3)
PC8: JP5.15 U1.47(PC.8/EBI_ADR16/I2C0_SDA/UART1_RXD/PWM1_CH1/BPWM1_CH4)
PC9: JP3.8 U1.8(PC.9/EBI_ADR7/PWM1_CH3)
PC10: JP3.7 U1.7(PC.10/EBI_ADR6/PWM1_CH2)
PC11: JP3.6 U1.6(PC.11/EBI_ADR5/UART0_RXD/I2C0_SDA/PWM1_CH1/ACMP1_O)
PC12: JP3.5 U1.5(PC.12/EBI_ADR4/UART0_TXD/I2C0_SCL/SC0_nCD/PWM1_CH0/ACMP0_O)
PC14: JP6.19 U1.115(PC.14/EBI_AD11/SPI0_I2SMCLK/USCI0_CTL0/QSPI0_CLK/USCI2_CLK/TM1)
PD0: JP4.27 U1.91(PD.0/EBI_AD13/USCI0_CLK/SPI0_MOSI/TM2)
PD1: JP4.26 U1.90(PD.1/EBI_AD12/USCI0_DAT0/SPI0_MISO)
PD2: JP4.25 U1.89(PD.2/EBI_AD11/USCI0_DAT1/SPI0_CLK/UART0_RXD)
PD3: JP4.24 U1.88(PD.3/EBI_AD10/USCI0_CTL1/SPI0_SS/USCI1_CTL0/UART0_TXD)
PD4_TK16: R21.1 SHILEDING1.1 U1.87(PD.4/USCI0_CTL0/I2C1_SDA/USCI1_CTL1/PSIO0_CH7)
PD5: JP4.22 U1.86(PD.5/I2C1_SCL/USCI1_DAT0/PSIO0_CH6)
PD6_TK14: K14.1 K14.2 R20.1 U1.85(PD.6/UART1_RXD/I2C0_SDA/USCI1_DAT1/PSIO0_CH5)
PD7_TK13: R19.2 TK13.1 U1.84(PD.7/UART1_TXD/I2C0_SCL/USCI1_CLK/PSIO0_CH4)
PD8: JP4.4 U1.68(PD.8/EBI_AD6/UART2_nRTS/PSIO0_CH3)
PD9: JP4.3 U1.67(PD.9/EBI_AD7/UART2_nCTS/PSIO0_CH2)
PD10: JP3.20 U1.20(PD.10/EBI_nCS2/UART1_RXD)
PD11: JP3.19 U1.19(PD.11/EBI_nCS1/UART1_TXD)
PD12: JP3.18 U1.18(PD.12/EBI_nCS0/UART2_RXD/BPWM0_CH5/CLKO/EADC0_ST/INT5)
PD13: JP4.28 U1.92(PD.13/EBI_AD10/SPI0_I2SMCLK/USCI2_CTL0)
PD15: JP5.22 U1.54(PD.15/PSIO0_CH7/PWM0_CH5/TM3/INT1)
PE0: JP6.10 U1.106(PE.0/EBI_AD11/QSPI0_MOSI0/I2C1_SDA/USCI2_DAT0)
PE1: JP6.9 U1.105(PE.1/EBI_AD10/QSPI0_MISO0/I2C1_SCL/USCI2_DAT1)
PE2: JP6.6 U1.102(PE.2/EBI_ALE/SC0_CLK/USCI0_CLK/USCI2_CTL0/PWM0_CH5/BPWM0_CH0)
PE3: JP6.5 U1.101(PE.3/EBI_MCLK/SC0_DAT/USCI0_DAT0/PWM0_CH4/BPWM0_CH1)
PE4: JP6.4 U1.100(PE.4/EBI_nWR/SC0_RST/USCI0_DAT1/PSIO0_CH3/PWM0_CH3/BPWM0_CH2)
PE5: JP6.3 U1.99(PE.5/EBI_nRD/SC0_PWR/USCI0_CTL1/PSIO0_CH2/PWM0_CH2/BPWM0_CH3)
PE6: JP6.2 U1.98(PE.6/SC0_nCD/USCI0_CTL0/PSIO0_CH1/PWM0_CH1/BPWM0_CH4)
PE7: JP6.1 U1.97(PE.7/PSIO0_CH0/PWM0_CH0/BPWM0_CH5)
PE8: JP5.9 U1.41(PE.8/EBI_ADR10/USCI1_CTL1/UART2_TXD/PWM0_CH0/PWM0_BRAKE0)
PE9: JP5.10 U1.42(PE.9/EBI_ADR11/USCI1_CTL0/UART2_RXD/PWM0_CH1/PWM0_BRAKE1)
PE10: JP5.11 U1.43(PE.10/EBI_ADR12/USCI1_DAT0/PWM0_CH2/PWM1_BRAKE0)
PE11: JP5.12 U1.44(PE.11/EBI_ADR13/USCI1_DAT1/UART1_nCTS/PWM0_CH3/PWM1_BRAKE1)
PE12: JP5.13 U1.45(PE.12/EBI_ADR14/USCI1_CLK/UART1_nRTS/PWM0_CH4)
PE13: JP5.14 U1.46(PE.13/EBI_ADR15/I2C0_SCL/UART1_TXD/PWM0_CH5/PWM1_CH0/BPWM1_CH5)
PE14: JP5.30 U1.62(PE.14/EBI_AD8/UART2_TXD/PSIO0_CH0)
PE15: JP5.31 U1.63(PE.15/EBI_AD9/UART2_RXD/PSIO0_CH1)
PF2_XT1_OUT: JP5.6 R5.2 U1.38(PF.2/EBI_nCS1/UART0_RXD/I2C0_SDA/QSPI0_CLK/XT1_OUT/BPWM1_CH1)
PF3_XT1_IN: JP5.5 R2.2 U1.37(PF.3/EBI_nCS0/UART0_TXD/I2C0_SCL/XT1_IN/BPWM1_CH0)
PF4_X32_OUT: JP3.32 R4.2 U1.32(PF.4/UART2_TXD/UART2_nRTS/PWM0_CH1/BPWM0_CH5/X32_OUT)
PF5_X32_IN: JP3.31 R1.2 U1.31(PF.5/UART2_RXD/UART2_nCTS/PWM0_CH0/BPWM0_CH4/X32_IN/EADC0_ST)
PF6: JP3.29 U1.29(PF.6/EBI_ADR19/SC0_CLK/SPI0_MOSI/EBI_nCS0/TAMPER0)
PF7: JP3.28 U1.28(PF.7/EBI_ADR18/SC0_DAT/SPI0_MISO)
PF15: JP5.29 U1.61(VDDIO)
RED: ICES2.2 ICEU1.62(PB.9)
SPIM_CLK: ICEU1.38(PC.2) ICEU4.7(B1)
SPIM_CLK_LV: ICEU2.6(CLK) ICEU4.2(A1)
SPIM_CS: ICEU1.37(PC.3) ICEU3.7(B1)
SPIM_CS_LV: ICEU2.1(CS#) ICEU3.2(A1)
SPIM_D2: ICEU1.35(PC.5)
SPIM_D3: ICEU1.36(PC.4)
SPIM_MISO0: ICEU1.39(PC.1) ICEU2.2(DO)
SPIM_MOSI0: ICEU1.40(PC.0) ICEU4.6(B2)
SPIM_MOSI0_LV: ICEU2.5(DI) ICEU4.3(A2)
SWO: ICEJ4.6 ICEU1.26(PA.4)
TICECLK: ICEJ4.5 ICEU1.9(PA.10) J1.6 JP4.2 R14.2 U1.66(PF.1/ICE_CLK)
TICEDAT: ICEJ4.3 ICEU1.10(PA.9) J1.4 JP4.1 R13.2 U1.65(PF.0/ICE_DAT)
TICERST: C9.2 ICEJ4.7 ICEU1.14(PF.5) J1.8 JP5.32 NU1.3(MCU_RESET) NU5.5(RESET) R3.2 SW1.2 U1.64(nRESET)
USB_D+: JP4.31 R11.1 U1.95(USB_D+)
USB_D-: JP4.30 R9.1 U1.94(USB_D-)
USB_HS_CAP: ICEC2.1 ICEU1.47(HSUSB_VDD12_CAP)
USB_HS_D+: ICER7.1 ICEU1.46(HSUSB_D+)
USB_HS_D-: ICER6.1 ICEU1.44(HSUSB_D-)
USB_HS_REXT: ICER1.1 ICEU1.41(HSUSB_VRES)
USB_HS_VBUS: ICED1.1 ICED3.2 ICEJ2.1 ICEJ3.1(VBUS) ICEU1.43(HSUSB_VBUS)
USB_VBUS: D1.1 HJ2.1(VBUS) J2.1(VBUS) R18.2
USB_VBUS_10R: C10.1 CT1.1 JP4.29 R18.1 U1.93(USB_VBUS)
USB_VDD33_CAP: C6.2 JP4.32 U1.96(USB_VDD33_CAP)
VLCD: C22.2 JP3.17 U1.17(NC)
VREF: C14.1 C15.2 JP6.25 L5.2 NU4.8(VREF) U1.121(VREF) VREF1.2
N16825237: LEDG1.1 R6.2
N16825240: LEDR1.1 R7.2
N16840819: ICEC6.1 ICEU1.24(LDO_CAP)
N16840960: ICEC3.1 ICEU1.50(LDO_CAP)
N17019924: ICER8.2 ICER9.2 ICEUP2.1(ADJ)
N17029977: ICERP1.8(R4) ICES3.1
N17029979: ICERP1.6(R3) ICES2.1
N17030004: ICERP1.4(R2) ICES1.1
N17030010: ICERP1.2(R1) ICES0.1
N17042369: ICEJ3.6(Shield) ICEJ3.7(Shield) ICEJ3.8(Shield) ICEJ3.9(Shield) ICEJ3.10(Shield) ICEJ3.11(Shield) ICEL2.2
N17110356: HJ2.6(Shield) HJ2.7(Shield) HJ2.8(Shield) HJ2.9(Shield) HJ2.10(Shield) HJ2.11(Shield) J2.6(Shield) J2.7(Shield) J2.8(Shield) J2.9(Shield) J2.10(Shield) J2.11(Shield) L3.2
N17125028: R12.2 SW2.1(A1)
N17155328: ICER18.1 ICEU2.7(HOLD#)
N17155343: ICER19.1 ICEU2.3(WP#)
N17159369: C8.2 R5.1 X1.1
N17159371: C2.2 R2.1 X1.2
N17159463: C1.2 R1.1 X2.1
N17159465: C7.2 R4.1 X2.2
N17167442: D2.1 UP2.2(OUT) UP2.4(OUT)

Not connected (* = marked no-connect by the designer): H1 1; H2 1; H3 1; H4 1; HJ2 4(ID)*; ICEJ3 4(ID)*; ICESW2 3(A3)* 6(B3)*; ICEU1 1(PB.6)* 2(PB.5)* 3(PB.4)* 4(PB.3)* 5(PB.2)* 8(PA.11)* 11(PA.8)* 20(PA.7)* 21(PA.6)* 25(PA.5)* 48(HSUSB_ID)* 60(PB.11)* 61(PB.10)* 64(PB.7)*; ICEU3 3(A2)* 6(B2)*; J1 1* 3* 5*; J2 4(ID)*; NU1 1(NC)*

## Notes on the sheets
sheet 1
- Off-page Connector
- DEBUG
- RESET
- SPI FLASH
- Nu-Trace,   ID0 = 1, ID1 = 1
  Nu-Link2,   ID0 = 0, ID1 = 1
  Nu-LInk2-Me, ID0 = 0, ID1 = 0
- NULINK ID
- KEY
- Power Switch
- VCOM SWITCH
- 12M Crystal
- USB 2.0 HIGH SPEED DEVICES
- LED
- ICE INTERFACE
sheet 2
- P1 - P32
- P65 - P96
- P33 - P64
- P97 - P128
- Mounting Hole
- ICE
- Bypass Cap
- RESET
- HXT & LXT Crystal
- LED
- USB Device
- Power
sheet 3
- P1 - P32
- P65 - P96
- P33 - P64
- P97 - P128
- UNO Interface
- External Connector
sheet 4
- Touch Keys offpage
- Touch Key reference
- PCB Touch Keys
- TOP SHILED
- Top Layer Shielding
